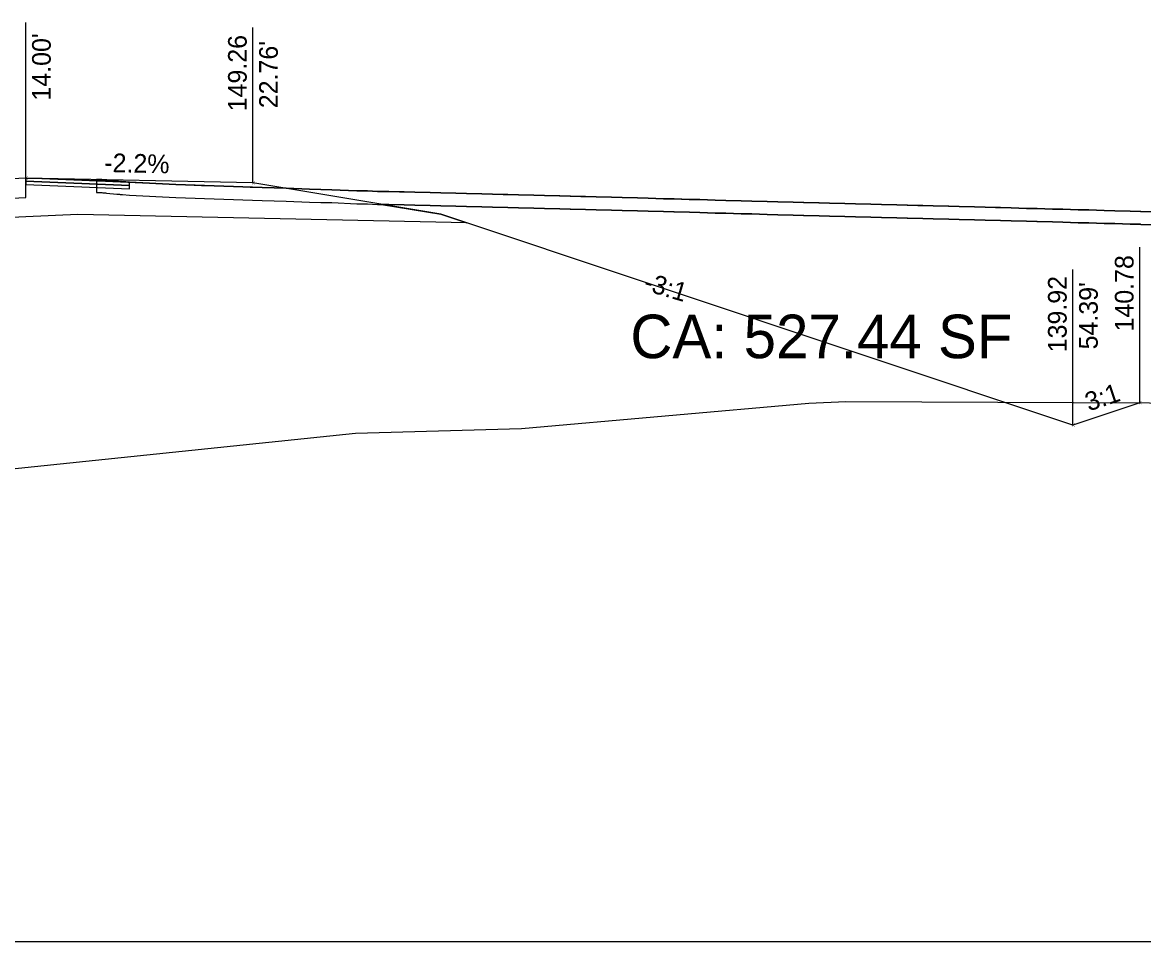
# Model space of a CAD drawing. Extents: x -26 to 4403, y -13 to 9578.
# Drawn here: x 1263.87 to 1307.11, y 7500 to 7535.45 of the extents above; entities that cross this region are included whole.
import ezdxf

# ---------------------------------------------------------------- set-up
doc = ezdxf.new("R2010")
doc.units = 0
for name, color, linetype in [('_CIVIL_CONSTRUCTION', 7, 'Continuous'), ('CONST_DCH', 7, 'Continuous'), ('CONST_LV3', 7, 'Continuous'), ('DTM_CORRIDOR', 7, 'Continuous'), ('DTM_P_FINISHED_GRADE', 7, 'Continuous'), ('DTM_TEMP_DROP', 7, 'Continuous'), ('DTM_X_GROUND', 7, 'Continuous'), ('XS_CELL', 7, 'Continuous'), ('XS_M_SHAPES_EARTHWORK', 7, 'Continuous'), ('XS_P_ASPHALT', 7, 'Continuous'), ('XS_P_DR_ASPHALT', 7, 'Continuous'), ('XS_P_DR_ASPHALT_B', 7, 'Continuous'), ('XS_P_DR_GRAVEL', 7, 'Continuous'), ('XS_P_GROUND', 7, 'Continuous'), ('XS_P_SHOULDER', 7, 'Continuous'), ('XS_P_SUBGRADE_GRANULAR', 7, 'Continuous'), ('XS_P_TX_CLEARZONE', 7, 'Continuous'), ('XS_P_TX_FS_BS', 7, 'Continuous'), ('XS_SHEET_EW_TX_AREA', 7, 'Continuous')]:
    doc.layers.add(name, color=color, linetype=linetype)

msp = doc.modelspace()

# ---------------------------------------------------------------- linework, layer by layer
at = {"layer": 'CONST_LV3'}
msp.add_lwpolyline([(1264, 7529.45), (1264.311, 7529.444), (1264.516, 7529.439), (1270.77, 7529.16), (1271.278, 7529.149), (1271.786, 7529.138), (1272.646, 7529.093), (1273.11, 7529.083), (1273.575, 7529.072), (1274.039, 7529.062), (1274.943, 7529.018), (1275.374, 7529.009), (1275.804, 7528.999), (1276.765, 7528.958), (1277.178, 7528.949), (1277.558, 7528.934), (1277.969, 7528.925), (1278, 7528.924), (1278.411, 7528.915), (1279, 7528.902), (1279.589, 7528.889), (1280, 7528.88), (1280.002, 7528.88), (1280.004, 7528.88), (1280.591, 7528.864), (1281, 7528.854), (1281.59, 7528.838), (1282, 7528.827), (1282.41, 7528.816), (1283, 7528.801), (1283.59, 7528.785), (1284, 7528.774), (1284.59, 7528.758), (1285, 7528.747), (1285.41, 7528.737), (1286, 7528.721), (1286.591, 7528.705), (1287, 7528.694), (1287.591, 7528.679), (1288, 7528.668), (1288.409, 7528.657), (1289, 7528.641), (1289.591, 7528.626), (1290, 7528.615), (1290.591, 7528.599), (1291, 7528.588), (1291.408, 7528.577), (1292, 7528.562), (1292.592, 7528.546), (1293, 7528.535), (1293.592, 7528.519), (1294, 7528.509), (1294.592, 7528.493), (1295, 7528.482), (1295.593, 7528.466), (1296, 7528.455), (1296.593, 7528.44), (1297, 7528.429), (1297.593, 7528.413), (1298, 7528.402), (1298.407, 7528.392), (1299, 7528.376), (1299.593, 7528.36), (1300, 7528.349), (1300.594, 7528.334), (1301, 7528.323), (1301.406, 7528.312), (1302, 7528.296), (1302.594, 7528.28), (1303, 7528.27), (1303.406, 7528.259), (1304, 7528.243), (1304.594, 7528.227), (1305, 7528.217), (1305.406, 7528.206), (1306, 7528.19), (1306.405, 7528.179), (1307, 7528.164), (1307.595, 7528.148)], dxfattribs=at)
at = {"layer": 'DTM_P_FINISHED_GRADE'}
for points in [[(1264, 7529.45), (1264.621, 7529.43), (1267.999, 7529.284)], [(1266.731, 7529.391), (1266.755, 7529.389), (1266.932, 7529.386), (1266.963, 7529.384), (1266.979, 7529.383), (1266.983, 7529.383), (1266.995, 7529.383), (1267.004, 7529.382), (1267.054, 7529.379), (1267.067, 7529.379), (1267.105, 7529.37), (1267.504, 7529.331), (1267.533, 7529.329), (1267.541, 7529.328), (1267.542, 7529.328), (1267.568, 7529.325), (1267.576, 7529.324), (1267.609, 7529.321), (1267.643, 7529.318), (1267.653, 7529.317), (1267.669, 7529.315), (1267.686, 7529.314), (1267.696, 7529.313), (1267.728, 7529.31), (1267.999, 7529.284), (1269.785, 7529.202), (1273.112, 7529.083), (1273.575, 7529.072), (1273.576, 7529.072), (1274.039, 7529.062), (1274.943, 7529.018), (1274.944, 7529.018), (1275.374, 7529.009), (1275.375, 7529.009), (1275.804, 7528.999), (1276.765, 7528.958), (1276.766, 7528.958), (1277.178, 7528.949), (1277.179, 7528.949), (1277.56, 7528.934), (1277.969, 7528.925), (1278, 7528.924), (1278.002, 7528.924), (1278.591, 7528.911), (1279, 7528.902), (1279.002, 7528.902), (1279.591, 7528.889), (1280, 7528.88), (1280.002, 7528.88), (1280.004, 7528.88), (1280.591, 7528.864), (1281, 7528.854), (1281.002, 7528.854), (1281.591, 7528.838), (1282, 7528.827), (1282.002, 7528.827), (1282.591, 7528.811), (1283, 7528.801), (1283.002, 7528.8), (1283.592, 7528.785), (1284, 7528.774), (1284.002, 7528.774), (1284.592, 7528.758), (1285, 7528.747), (1285.002, 7528.747), (1285.592, 7528.732), (1286, 7528.721), (1286.002, 7528.721), (1286.592, 7528.705), (1287, 7528.694), (1287.002, 7528.694), (1287.592, 7528.679), (1288, 7528.668), (1288.002, 7528.668), (1288.593, 7528.652), (1289, 7528.641), (1289.002, 7528.641), (1289.593, 7528.626), (1290, 7528.615), (1290.002, 7528.615), (1290.593, 7528.599), (1291, 7528.588), (1291.002, 7528.588), (1291.593, 7528.572), (1292, 7528.562), (1292.002, 7528.562), (1292.593, 7528.546), (1293, 7528.535), (1293.002, 7528.535), (1293.594, 7528.519), (1294, 7528.509), (1294.002, 7528.509), (1294.594, 7528.493), (1295, 7528.482), (1295.002, 7528.482), (1295.594, 7528.466), (1296, 7528.455), (1296.002, 7528.455), (1296.594, 7528.44), (1297, 7528.429), (1297.002, 7528.429), (1297.594, 7528.413), (1298, 7528.402), (1298.002, 7528.402), (1298.595, 7528.387), (1299, 7528.376), (1299.002, 7528.376), (1299.595, 7528.36), (1300, 7528.349), (1300.002, 7528.349), (1300.595, 7528.334), (1301, 7528.323), (1301.002, 7528.323), (1301.595, 7528.307), (1302, 7528.296), (1302.002, 7528.296), (1302.595, 7528.28), (1303, 7528.27), (1303.002, 7528.27), (1303.596, 7528.254), (1304, 7528.243), (1304.002, 7528.243), (1304.596, 7528.227), (1305, 7528.217), (1305.002, 7528.217), (1305.596, 7528.201), (1306, 7528.19), (1306.002, 7528.19), (1306.596, 7528.174), (1307, 7528.164), (1307.002, 7528.163), (1307.596, 7528.148)]]:
    msp.add_lwpolyline(points, dxfattribs=at)
at = {"layer": 'DTM_X_GROUND'}
msp.add_lwpolyline([(1159.518, 7517.394), (1200.052, 7515.401), (1217.74, 7513.76), (1222.892, 7513.417), (1226.763, 7513.627), (1241.699, 7515.779), (1244.696, 7517.139), (1249.906, 7516.828), (1249.956, 7516.833), (1276.709, 7519.611), (1283.124, 7519.79), (1294.202, 7520.766), (1295.632, 7520.835), (1310.279, 7520.767), (1331.863, 7520.749), (1369.14, 7520.527), (1389.173, 7520.495), (1400, 7520.407)], dxfattribs=at)
at = {"layer": 'XS_CELL'}
msp.add_line((1250, 7500), (1400, 7500), dxfattribs=at)
at = {"layer": 'XS_M_SHAPES_EARTHWORK'}
for points in [[(1307.596, 7527.648), (1307.002, 7527.663), (1307, 7527.664), (1306.596, 7527.674), (1306.002, 7527.69), (1306, 7527.69), (1305.596, 7527.701), (1305.002, 7527.717), (1305, 7527.717), (1304.596, 7527.727), (1304.002, 7527.743), (1304, 7527.743), (1303.596, 7527.754), (1303.002, 7527.77), (1303, 7527.77), (1302.595, 7527.78), (1302.002, 7527.796), (1302, 7527.796), (1301.595, 7527.807), (1301.002, 7527.823), (1301, 7527.823), (1300.595, 7527.834), (1300.002, 7527.849), (1300, 7527.849), (1299.595, 7527.86), (1299.002, 7527.876), (1299, 7527.876), (1298.595, 7527.887), (1298.002, 7527.902), (1298, 7527.902), (1297.594, 7527.913), (1297.002, 7527.929), (1297, 7527.929), (1296.594, 7527.94), (1296.002, 7527.955), (1296, 7527.955), (1295.594, 7527.966), (1295.002, 7527.982), (1295, 7527.982), (1294.594, 7527.993), (1294.002, 7528.009), (1294, 7528.009), (1293.594, 7528.019), (1293.002, 7528.035), (1293, 7528.035), (1292.593, 7528.046), (1292.002, 7528.062), (1292, 7528.062), (1291.593, 7528.072), (1291.002, 7528.088), (1291, 7528.088), (1290.593, 7528.099), (1290.002, 7528.115), (1290, 7528.115), (1289.593, 7528.126), (1289.002, 7528.141), (1289, 7528.141), (1288.593, 7528.152), (1288.002, 7528.168), (1288, 7528.168), (1287.592, 7528.179), (1287.002, 7528.194), (1287, 7528.194), (1286.592, 7528.205), (1286.002, 7528.221), (1286, 7528.221), (1285.592, 7528.232), (1285.002, 7528.247), (1285, 7528.247), (1284.592, 7528.258), (1284.002, 7528.274), (1284, 7528.274), (1283.592, 7528.285), (1283.002, 7528.3), (1283, 7528.301), (1282.591, 7528.311), (1282.002, 7528.327), (1282, 7528.327), (1281.591, 7528.338), (1281.002, 7528.354), (1281, 7528.354), (1280.591, 7528.364), (1280.004, 7528.38), (1280.002, 7528.38), (1280, 7528.38), (1279.591, 7528.389), (1279.002, 7528.402), (1279, 7528.402), (1278.591, 7528.411), (1278.002, 7528.424), (1278, 7528.424), (1277.969, 7528.425), (1277.721, 7528.43), (1280, 7528.051), (1281.003, 7527.716), (1266, 7528.046), (1264, 7527.95), (1250, 7527.278)], [(1249.956, 7516.833), (1276.709, 7519.611), (1283.124, 7519.79), (1294.202, 7520.766), (1295.632, 7520.835), (1310.279, 7520.767), (1331.863, 7520.749), (1369.14, 7520.527)]]:
    msp.add_lwpolyline(points, dxfattribs=at)
at = {"layer": 'XS_P_ASPHALT'}
msp.add_lwpolyline([(1250, 7528.778), (1236, 7528.106), (1236, 7528.106), (1236, 7527.356), (1250, 7528.028), (1250, 7528.028), (1264, 7528.7), (1264, 7528.7), (1264, 7529.45), (1264, 7529.45), (1264, 7529.45), (1250, 7528.778), (1250, 7528.778)], dxfattribs=at)
at = {"layer": 'XS_P_DR_ASPHALT'}
msp.add_lwpolyline([(1264, 7529.45), (1264, 7529.325), (1264.621, 7529.305), (1267.999, 7529.159), (1267.999, 7529.284), (1264.621, 7529.43), (1264, 7529.45)], dxfattribs=at)
at = {"layer": 'XS_P_DR_ASPHALT_B'}
msp.add_lwpolyline([(1264, 7529.325), (1264, 7529.2), (1264.621, 7529.18), (1267.999, 7529.034), (1267.999, 7529.159), (1264.621, 7529.305), (1264, 7529.325)], dxfattribs=at)
at = {"layer": 'XS_P_DR_GRAVEL'}
for points in [[(1266.731, 7529.391), (1266.731, 7528.891), (1266.755, 7528.889), (1266.932, 7528.886), (1266.963, 7528.884), (1266.979, 7528.883), (1266.983, 7528.883), (1266.995, 7528.883), (1267.004, 7528.882), (1267.054, 7528.879), (1267.067, 7528.879), (1267.105, 7528.87), (1267.504, 7528.831), (1267.533, 7528.829), (1267.541, 7528.828), (1267.542, 7528.828), (1267.568, 7528.825), (1267.576, 7528.824), (1267.609, 7528.821), (1267.643, 7528.818), (1267.653, 7528.817), (1267.669, 7528.815), (1267.686, 7528.814), (1267.696, 7528.813), (1267.728, 7528.81), (1267.999, 7528.784), (1269.785, 7528.702), (1273.112, 7528.583), (1273.575, 7528.572), (1273.576, 7528.572), (1274.039, 7528.562), (1274.943, 7528.518), (1274.944, 7528.518), (1275.374, 7528.509), (1275.375, 7528.509), (1275.804, 7528.499), (1276.765, 7528.458), (1276.766, 7528.458), (1277.178, 7528.449), (1277.179, 7528.449), (1277.56, 7528.434), (1277.969, 7528.425), (1278, 7528.424), (1278.002, 7528.424), (1278.591, 7528.411), (1279, 7528.402), (1279.002, 7528.402), (1279.591, 7528.389), (1280, 7528.38), (1280.002, 7528.38), (1280.004, 7528.38), (1280.591, 7528.364), (1281, 7528.354), (1281.002, 7528.354), (1281.591, 7528.338), (1282, 7528.327), (1282.002, 7528.327), (1282.591, 7528.311), (1283, 7528.301), (1283.002, 7528.3), (1283.592, 7528.285), (1284, 7528.274), (1284.002, 7528.274), (1284.592, 7528.258), (1285, 7528.247), (1285.002, 7528.247), (1285.592, 7528.232), (1286, 7528.221), (1286.002, 7528.221), (1286.592, 7528.205), (1287, 7528.194), (1287.002, 7528.194), (1287.592, 7528.179), (1288, 7528.168), (1288.002, 7528.168), (1288.593, 7528.152), (1289, 7528.141), (1289.002, 7528.141), (1289.593, 7528.126), (1290, 7528.115), (1290.002, 7528.115), (1290.593, 7528.099), (1291, 7528.088), (1291.002, 7528.088), (1291.593, 7528.072), (1292, 7528.062), (1292.002, 7528.062), (1292.593, 7528.046), (1293, 7528.035), (1293.002, 7528.035), (1293.594, 7528.019), (1294, 7528.009), (1294.002, 7528.009), (1294.594, 7527.993), (1295, 7527.982), (1295.002, 7527.982), (1295.594, 7527.966), (1296, 7527.955), (1296.002, 7527.955), (1296.594, 7527.94), (1297, 7527.929), (1297.002, 7527.929), (1297.594, 7527.913), (1298, 7527.902), (1298.002, 7527.902), (1298.595, 7527.887), (1299, 7527.876), (1299.002, 7527.876), (1299.595, 7527.86), (1300, 7527.849), (1300.002, 7527.849), (1300.595, 7527.834), (1301, 7527.823), (1301.002, 7527.823), (1301.595, 7527.807), (1302, 7527.796), (1302.002, 7527.796), (1302.595, 7527.78), (1303, 7527.77), (1303.002, 7527.77), (1303.596, 7527.754), (1304, 7527.743), (1304.002, 7527.743), (1304.596, 7527.727), (1305, 7527.717), (1305.002, 7527.717), (1305.596, 7527.701), (1306, 7527.69), (1306.002, 7527.69), (1306.596, 7527.674), (1307, 7527.664), (1307.002, 7527.663), (1307.596, 7527.648)], [(1307.596, 7528.148), (1307.002, 7528.163), (1307, 7528.164), (1306.596, 7528.174), (1306.002, 7528.19), (1306, 7528.19), (1305.596, 7528.201), (1305.002, 7528.217), (1305, 7528.217), (1304.596, 7528.227), (1304.002, 7528.243), (1304, 7528.243), (1303.596, 7528.254), (1303.002, 7528.27), (1303, 7528.27), (1302.595, 7528.28), (1302.002, 7528.296), (1302, 7528.296), (1301.595, 7528.307), (1301.002, 7528.323), (1301, 7528.323), (1300.595, 7528.334), (1300.002, 7528.349), (1300, 7528.349), (1299.595, 7528.36), (1299.002, 7528.376), (1299, 7528.376), (1298.595, 7528.387), (1298.002, 7528.402), (1298, 7528.402), (1297.594, 7528.413), (1297.002, 7528.429), (1297, 7528.429), (1296.594, 7528.44), (1296.002, 7528.455), (1296, 7528.455), (1295.594, 7528.466), (1295.002, 7528.482), (1295, 7528.482), (1294.594, 7528.493), (1294.002, 7528.509), (1294, 7528.509), (1293.594, 7528.519), (1293.002, 7528.535), (1293, 7528.535), (1292.593, 7528.546), (1292.002, 7528.562), (1292, 7528.562), (1291.593, 7528.572), (1291.002, 7528.588), (1291, 7528.588), (1290.593, 7528.599), (1290.002, 7528.615), (1290, 7528.615), (1289.593, 7528.626), (1289.002, 7528.641), (1289, 7528.641), (1288.593, 7528.652), (1288.002, 7528.668), (1288, 7528.668), (1287.592, 7528.679), (1287.002, 7528.694), (1287, 7528.694), (1286.592, 7528.705), (1286.002, 7528.721), (1286, 7528.721), (1285.592, 7528.732), (1285.002, 7528.747), (1285, 7528.747), (1284.592, 7528.758), (1284.002, 7528.774), (1284, 7528.774), (1283.592, 7528.785), (1283.002, 7528.8), (1283, 7528.801), (1282.591, 7528.811), (1282.002, 7528.827), (1282, 7528.827), (1281.591, 7528.838), (1281.002, 7528.854), (1281, 7528.854), (1280.591, 7528.864), (1280.004, 7528.88), (1280.002, 7528.88), (1280, 7528.88), (1279.591, 7528.889), (1279.002, 7528.902), (1279, 7528.902), (1278.591, 7528.911), (1278.002, 7528.924), (1278, 7528.924), (1277.969, 7528.925), (1277.56, 7528.934), (1277.179, 7528.949), (1277.178, 7528.949), (1276.766, 7528.958), (1276.765, 7528.958), (1275.804, 7528.999), (1275.375, 7529.009), (1275.374, 7529.009), (1274.944, 7529.018), (1274.943, 7529.018), (1274.039, 7529.062), (1273.576, 7529.072), (1273.575, 7529.072), (1273.112, 7529.083), (1269.785, 7529.202), (1267.999, 7529.284), (1267.728, 7529.31), (1267.696, 7529.313), (1267.686, 7529.314), (1267.669, 7529.315), (1267.653, 7529.317), (1267.643, 7529.318), (1267.609, 7529.321), (1267.576, 7529.324), (1267.568, 7529.325), (1267.542, 7529.328), (1267.541, 7529.328), (1267.533, 7529.329), (1267.504, 7529.331), (1267.105, 7529.37), (1267.067, 7529.379), (1267.054, 7529.379), (1267.004, 7529.382), (1266.995, 7529.383), (1266.983, 7529.383), (1266.979, 7529.383), (1266.963, 7529.384), (1266.932, 7529.386), (1266.755, 7529.389), (1266.731, 7529.391)]]:
    msp.add_lwpolyline(points, dxfattribs=at)
at = {"layer": 'XS_P_GROUND'}
for points in [[(1304.386, 7519.923), (1304.386, 7519.923), (1280, 7528.051), (1280, 7528.051), (1272.759, 7529.258)], [(1306.966, 7520.783), (1306.732, 7520.705), (1304.386, 7519.923)]]:
    msp.add_lwpolyline(points, dxfattribs=at)
at = {"layer": 'XS_P_SHOULDER'}
msp.add_lwpolyline([(1272.759, 7529.258), (1272.759, 7529.258), (1264, 7529.45)], dxfattribs=at)
at = {"layer": 'XS_P_SUBGRADE_GRANULAR'}
for points in [[(1264, 7527.95), (1264, 7527.95), (1250, 7527.278)], [(1281.003, 7527.716), (1281.003, 7527.716), (1266, 7528.046), (1266, 7528.046), (1264, 7527.95)]]:
    msp.add_lwpolyline(points, dxfattribs=at)
at = {"layer": 'XS_P_TX_CLEARZONE'}
for p, q in [((1264, 7529.45), (1264, 7535.45)), ((1264, 7529.45), (1264, 7535.45)), ((1264, 7529.45), (1264, 7535.45)), ((1264, 7529.45), (1264, 7535.45)), ((1264, 7529.45), (1264, 7535.45)), ((1264, 7529.45), (1264, 7535.45)), ((1272.759, 7529.258), (1272.759, 7535.258)), ((1272.759, 7529.258), (1272.759, 7535.258)), ((1272.759, 7529.258), (1272.759, 7535.258)), ((1272.759, 7529.258), (1272.759, 7535.258)), ((1272.759, 7529.258), (1272.759, 7535.258)), ((1272.759, 7529.258), (1272.759, 7535.258)), ((1306.966, 7520.783), (1306.966, 7526.783)), ((1306.966, 7520.783), (1306.966, 7526.783)), ((1306.966, 7520.783), (1306.966, 7526.783)), ((1304.386, 7519.923), (1304.386, 7525.923)), ((1304.386, 7519.923), (1304.386, 7525.923)), ((1304.386, 7519.923), (1304.386, 7525.923))]:
    msp.add_line(p, q, dxfattribs=at)

# ---------------------------------------------------------------- texts
at = {"layer": '_CIVIL_CONSTRUCTION'}
msp.add_text('X', height=0.12, dxfattribs=at).set_placement((1263.961, 7529.39))
at = {"layer": 'CONST_DCH'}
msp.add_text('X', height=0.12, dxfattribs=at).set_placement((1304.347, 7519.863))
at = {"layer": 'DTM_CORRIDOR'}
msp.add_text('X', height=0.12, dxfattribs=at).set_placement((1306.927, 7520.723))
at = {"layer": 'DTM_TEMP_DROP'}
msp.add_text('X', height=0.12, dxfattribs=at).set_placement((1272.719, 7529.198))
at = {"layer": 'XS_P_TX_CLEARZONE'}
for s, p in [("14.00'", (1264.96, 7532.436)), ("14.00'", (1264.96, 7532.436)), ("14.00'", (1264.96, 7532.436)), ("14.00'", (1264.96, 7532.436)), ("14.00'", (1264.96, 7532.436)), ("14.00'", (1264.96, 7532.436)), ('149.26', (1272.519, 7532.022)), ('149.26', (1272.519, 7532.022)), ('149.26', (1272.519, 7532.022)), ('149.26', (1272.519, 7532.022)), ('149.26', (1272.519, 7532.022)), ('149.26', (1272.519, 7532.022)), ("22.76'", (1273.719, 7532.141)), ("22.76'", (1273.719, 7532.141)), ("22.76'", (1273.719, 7532.141)), ("22.76'", (1273.719, 7532.141)), ("22.76'", (1273.719, 7532.141)), ("22.76'", (1273.719, 7532.141)), ('140.78', (1306.726, 7523.53)), ('140.78', (1306.726, 7523.53)), ('140.78', (1306.726, 7523.53)), ('139.92', (1304.146, 7522.727)), ('139.92', (1304.146, 7522.727)), ('139.92', (1304.146, 7522.727)), ("54.39'", (1305.346, 7522.84)), ("54.39'", (1305.346, 7522.84)), ("54.39'", (1305.346, 7522.84))]:
    msp.add_text(s, height=0.72, rotation=90, dxfattribs=at).set_placement(p)
at = {"layer": 'XS_P_TX_FS_BS'}
for s, rotation, p in [('-2.2%', 358.7397, (1267.018, 7529.684)), ('-2.2%', 358.7397, (1267.018, 7529.684)), ('-2.2%', 358.7397, (1267.018, 7529.684)), ('-3:1', 343.5558, (1287.787, 7525.135)), ('-3:1', 343.5558, (1287.787, 7525.135)), ('-3:1', 343.5558, (1287.787, 7525.135)), ('3:1', 18.4349, (1305, 7520.444)), ('3:1', 18.4349, (1305, 7520.444)), ('3:1', 18.4349, (1305, 7520.444))]:
    msp.add_text(s, height=0.72, rotation=rotation, dxfattribs=at).set_placement(p)
at = {"layer": 'XS_SHEET_EW_TX_AREA'}
msp.add_text('CA: 527.44 SF', height=1.68, dxfattribs=at).set_placement((1287.318, 7522.5))

doc.saveas('drawing.dxf')
